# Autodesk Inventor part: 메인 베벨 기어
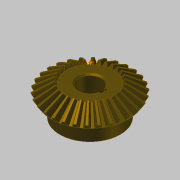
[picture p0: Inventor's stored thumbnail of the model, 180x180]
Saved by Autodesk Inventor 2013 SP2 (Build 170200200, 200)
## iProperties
Created: 2016-04
Part Number: 메인 베벨 기어
Material: 강철, 탄소
Document SubType Name: Modeling
Designer: mdu
Categories: <?xml version="1.0" encoding="UTF-16"?> <MemberInstance><Categories><FamilyTemplate><FamilyTemplateParameter ValueType="xs:double" Id="1" ObjectReferenceKey="da
Mass: 269.583 g
Surface Area: 108.837 cm^2
Volume: 34.2981 cm^3
Density: 7.86 g/cm^3
CustomPartVersion: 1
Author: mdu
Revision Number: 1
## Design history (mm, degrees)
node "맨 위 점"
node "메쉬 평면2"
sketch "톱니 본체 스케치"
  geometry: L1 (0, 0)-(28.669, -21.997); L2 (28.669, -21.997)-(31.109, -18.336); L3 (31.109, -18.336)-(0, 0); L4 (30, -20)-(0, 0); L5 (17.219, -13.212)-(18.685, -11.013); L6 (28.669, -21.997)-(17.219, -13.212); L7 (31.109, -18.336)-(18.685, -11.013); L8 (0, -39.387)-(0, 6.564) reference; L9 (0, -20)-(31.109, -20)
  constraints: 16 end point, 4 point on line, 3 perpendicular, 2 collinear, 1 horizontal alignment, 1 vertical alignment
  dimensions: "d0" = 60 diameter of L4.start L8 (= da_de); "d1" = 57.33744 diameter of L1.end L8 (= da_dfe); "d2" = 62.2188 diameter of L2.end L8 (= da_dae); "d3" = 14.4 distance between parallel lines of L2 L5 (= da_b); "d4" = 18.3359 vertical distance of L2.end L1.start (= da_ve)
revolve "톱니 본체" sketch "톱니 본체 스케치" stored, may be unused: angle "d5" = 90 deg
node "시작점"
node "톱니 평면"
sketch "시작 스케치"
  geometry: L1 (0, -23.505)-(0, 10.645) reference; L2 (-0.709, -2.928)-(0.709, -2.928); A1 r 19.188 centre (-19.457, -7.014) between (-0.709, -2.928) and (-3.232, 3.229); A2 r 19.188 centre (19.457, -7.014) between (3.232, 3.229) and (0.709, -2.928); A3 r 57.403 centre (0, -54.083) between (3.232, 3.229) and (-3.232, 3.229); 1 further point
  constraints: 6 point on circle, 3 centre point, 3 symmetric about line, 2 end point, 1 coincident, 1 perpendicular, 1 other
  dimensions: "d7" = 19.18795 radius of A1 (= fd_rr); "d8" = 19.45712 horizontal distance of point (0, -54.083) A1.centre (= fd_x); "d9" = 47.06905 vertical distance of point (0, -54.083) A1.centre (= fd_y); "d57" = 57.40327 radius of A3 (= 0.5 x fd_dva + 0.3 x da_he); "d58" = 51.15527 distance from line of A3.centre L2 (= 0.5 x fd_dva - 1.12 x da_he)
node "끝점"
  node "끝 평면"
sketch "3D 스케치 오른쪽"
  node "Helical Curve Right" dims "d65" = 229.90621 (computed from da_dm, da_delta, da_beta), "d66" = 31.5, "d67" = 60 (= da_de), "d68" = -9.82794 (= -da_delta), "d69" = 8.10972 (computed from fd_loft, da_delta)
node "끝 평면 오른쪽"
sketch "끝 스케치 오른쪽"
  geometry: L1 (0, -41.54)-(0, 13.178) reference; L2 (-0.422, -1.69)-(0.422, -1.69); A1 r 11.427 centre (-11.587, -4.123) between (-0.422, -1.69) and (-1.925, 1.977); A2 r 11.427 centre (11.587, -4.123) between (1.925, 1.977) and (0.422, -1.69); A3 r 34.184 centre (0, -32.153) between (1.925, 1.977) and (-1.925, 1.977); 1 further point
  constraints: 6 point on circle, 3 centre point, 3 symmetric about line, 2 end point, 1 coincident, 1 perpendicular, 1 other
  dimensions: "d70" = 11.58699 horizontal distance of A3.centre A1.centre (computed from fd_x, fd_ratio); "d71" = 28.03028 vertical distance of point (0, -32.153) A1.centre (computed from fd_y, fd_ratio); "d72" = 11.4267 radius of A1 (computed from fd_rr, fd_ratio); "d73" = 30.46369 distance from line of point (0, -32.153) L2 (computed from d58, fd_ratio); "d74" = 34.18446 radius of A3 (computed from d57, fd_ratio)
feature "로프트 오른쪽" sketch "끝 스케치 오른쪽" dims "d75" = 0, "d77" = 0, "d79" = 0, "d80" = 90 deg, "d85" = 20, "d92" = 90 deg, "d93" = 90 deg, "da_teethtype" = 0 [user parameter]
sketch "3D 스케치 왼쪽"
  node "Helical Curve Left" dims "d26" = 229.90621 (computed from da_dm, da_delta, da_beta), "d27" = 8.10972 (computed from fd_loft, da_delta), "d28" = 60 (= da_de), "d29" = -9.82794 (= -da_delta)
node "끝 평면 왼쪽"
sketch "끝 스케치 왼쪽" dims "d56" = 10.3728 (derived)
  geometry: L1 (0, -43.753)-(0, 15.405) reference; L2 (-0.422, -1.678)-(0.422, -1.678); A1 r 11.427 centre (-11.587, -4.111) between (-0.422, -1.678) and (-1.925, 1.988); A2 r 11.427 centre (11.587, -4.111) between (1.925, 1.988) and (0.422, -1.678); A3 r 34.184 centre (0, -32.142) between (1.925, 1.988) and (-1.925, 1.988); 2 further points; 1 other entity
  constraints: 6 point on circle, 3 centre point, 3 symmetric about line, 2 end point, 1 coincident, 2 other
  dimensions: "d30" = 11.4267 radius of A1 (computed from fd_rr, fd_ratio); "d31" = 11.58699 horizontal distance of point (0, -32.142) A1.centre (computed from fd_x, fd_ratio); "d32" = 28.03028 vertical distance of A1.centre point (0, -32.142) (computed from fd_y, fd_ratio); "d61" = 34.18446 radius of A3 (computed from d57, fd_ratio); "d62" = 30.46369 distance from line of point (0, -32.142) L2 (computed from d58, fd_ratio)
feature "로프트 왼쪽" sketch "끝 스케치 왼쪽" dims "d35" = 0, "d37" = 0, "d39" = 0, "d40" = 90 deg, "d84" = 10, "d90" = 90 deg, "d91" = 90 deg, "da_teethtype" = 0 [user parameter]
sketch "본체 스케치"
  geometry: L1 (0, -35.038)-(0, -19.531) reference; L2 (28.669, -21.997)-(17.219, -13.212) reference; L3 (17.219, -13.212)-(0, -13.212); L4 (28.669, -21.997)-(0, -21.997)
  constraints: 4 end point, 2 perpendicular, 2 point on line
revolve "본체 고정" sketch "본체 스케치" stored, may be unused: angle "d46" = 90 deg
feature "피치 지름" dims angle "d47" = 90 deg
sketch "스케치8"
  geometry: C1 r 22.5 at (0, 0); 1 further point
  constraints: 1 centre point, 1 coincident
  dimensions: "d94" = 45 diameter of C1
extrude "돌출1" join sketch "스케치8" distance "d95" = 13; taper "d96" = 0 deg
sketch "스케치9"
  geometry: 1 further point
hole "구멍1" sketch "스케치9" at (0, 0) diameter "d97" = 17; stored, may be unused: countersink angle "d101" = 90 deg, drill point angle "d103" = 118 deg; dims "d98" = 6, "d99" = 4, "d100" = 2, "d102" = 8
sketch "스케치10"
  geometry: L1 (8.124, 2.5)-(10.8, 2.5); L2 (10.8, 2.5)-(10.8, -2.5); L3 (10.8, -2.5)-(8.124, -2.5); A1 r 8.5 centre (0, 0) between (8.124, 2.5) and (8.124, -2.5) reference; 1 further point
  constraints: 6 end point, 2 parallel, 2 point on circle, 1 horizontal, 1 perpendicular
  dimensions: "d104" = 5 distance of L1.end L2.end; "d112" = 19.3 dimension on A1 L2
extrude "돌출2" cut sketch "스케치10" stored distance "d106" = 10; taper "d107" = 0 deg
chamfer "모따기1" distance "d108" = 1; stored, may be unused: second distance "d109" = 2, angle "d110" = 45 deg
fillet "모깎기1" dims "d111" = 2
body "Solid1"
feature "로프트" dims "d17" = 0, "d18" = 90 deg, "d19" = 0, "d20" = 90 deg, "d89" = 0, "da_teethtype" = 0 [user parameter]
pattern_circular "원형 패턴" dims angle "d22" = 360 deg, "d88" = 0, "da_teethtype" = 0 [user parameter]
pattern_circular "원형 패턴 오른쪽" dims angle "d82" = 360 deg, "da_teethtype" = 0 [user parameter]
pattern_circular "원형 패턴 왼쪽" dims angle "d42" = 360 deg, "da_teethtype" = 0 [user parameter]
sketch "끝 스케치"
  geometry: L1 (0, -15.359)-(0, 6.983) reference; L2 (-0.422, -1.69)-(0.422, -1.69); A1 r 11.427 centre (-11.587, -4.123) between (-0.422, -1.69) and (-1.925, 1.977); A2 r 11.427 centre (11.587, -4.123) between (1.925, 1.977) and (0.422, -1.69); A3 r 34.184 centre (0, -32.153) between (1.925, 1.977) and (-1.925, 1.977); 1 further point
  constraints: 6 point on circle, 3 centre point, 3 symmetric about line, 2 end point, 1 coincident, 1 other
  dimensions: "d12" = 11.4267 radius of A1 (computed from fd_rr, fd_ratio); "d15" = 11.58699 horizontal distance of A1.centre point (0, -32.153) (computed from fd_x, fd_ratio); "d16" = 28.03028 vertical distance of A1.centre point (0, -32.153) (computed from fd_y, fd_ratio); "d59" = 34.18446 radius of A3 (computed from d57, fd_ratio); "d60" = 30.46369 distance from line of A3.centre L2 (computed from d58, fd_ratio)
sketch "Sketch6"
  geometry: L1 (30, -20)-(0, 0) reference; L2 (0, -37.8)-(0, 6.3) reference
body "Srf1"
other parameters: "da_b" = 14.4 [user parameter; used in 2 equation terms], "da_de" = 60 [user parameter; used in 4 equation terms], "da_dae" = 62.2188 [user parameter; used in 2 equation terms], "da_dfe" = 57.33744 [user parameter; used in 1 equation term], "da_le" = 36.05551 [user parameter; used in 1 equation term], "da_omega" = 90 deg [user parameter; used in 1 equation term], "da_beta" = 0 [user parameter; used in 2 equation terms], "da_delta" = 9.82794 [user parameter; used in 8 equation terms], "da_alpha" = 20 deg [user parameter; used in 2 equation terms], "da_he" = 4.4 [user parameter; used in 4 equation terms], "da_ve" = 18.3359 [user parameter; used in 1 equation term], "fd_dv" = 108.16654 (computed from da_de, da_delta) [user parameter; used in 1 equation term], "fd_dva" = 112.16654 (computed from da_dae, da_delta) [user parameter; used in 3 equation terms], "fd_dvb" = 101.6433 (computed from fd_dv, da_alpha) [user parameter; used in 2 equation terms], "da_zv" = 540.83269 [user parameter; used in 1 equation term], "fd_loft" = 14.62 (= da_b + 0.05 x da_he) [user parameter; used in 4 equation terms], "fd_ratio" = 5.95514 (computed from da_le, fd_loft) [user parameter; used in 15 equation terms], "fd_rr" = 19.18795 (computed from fd_dd, fd_dvb) [user parameter; used in 6 equation terms], "fd_angle" = 0.29367 (computed from da_zv) [user parameter; used in 4 equation terms], "fd_x1" = 1.58802 (computed from da_dvw, fd_angle) [user parameter; used in 1 equation term], "fd_y1" = 54.05995 (computed from da_dvw, fd_angle) [user parameter; used in 1 equation term], "fd_x2" = 17.8691 (computed from fd_rr, fd_angle2, fd_angle) [user parameter; used in 1 equation term], "fd_y2" = 6.9909 (computed from fd_rr, fd_angle2, fd_angle) [user parameter; used in 1 equation term], "fd_x" = 19.45712 (= fd_x1 + fd_x2) [user parameter; used in 4 equation terms], "fd_y" = 47.06905 (= fd_y1 - fd_y2) [user parameter; used in 4 equation terms], "fd_angle2" = 3.43555 (computed from fd_dvb, fd_dd, da_alpha) [user parameter; used in 2 equation terms], "fd_dd" = 108.64654 (= fd_dva - 0.8 x da_he) [user parameter; used in 2 equation terms], "da_dvw" = 108.16654 [user parameter; used in 2 equation terms], "d11" = 14.62 (= fd_loft), "da_dm" = 48.01848 [user parameter; used in 2 equation terms], "da_x" = 0 [user parameter], "da_m" = 2 [user parameter], "d48" = 0, "d49" = 0, "d50" = 90 deg (= da_omega), "d51" = 6 deg (computed from da_z), "d52" = 0, "d53" = 0, "d54" = 0
